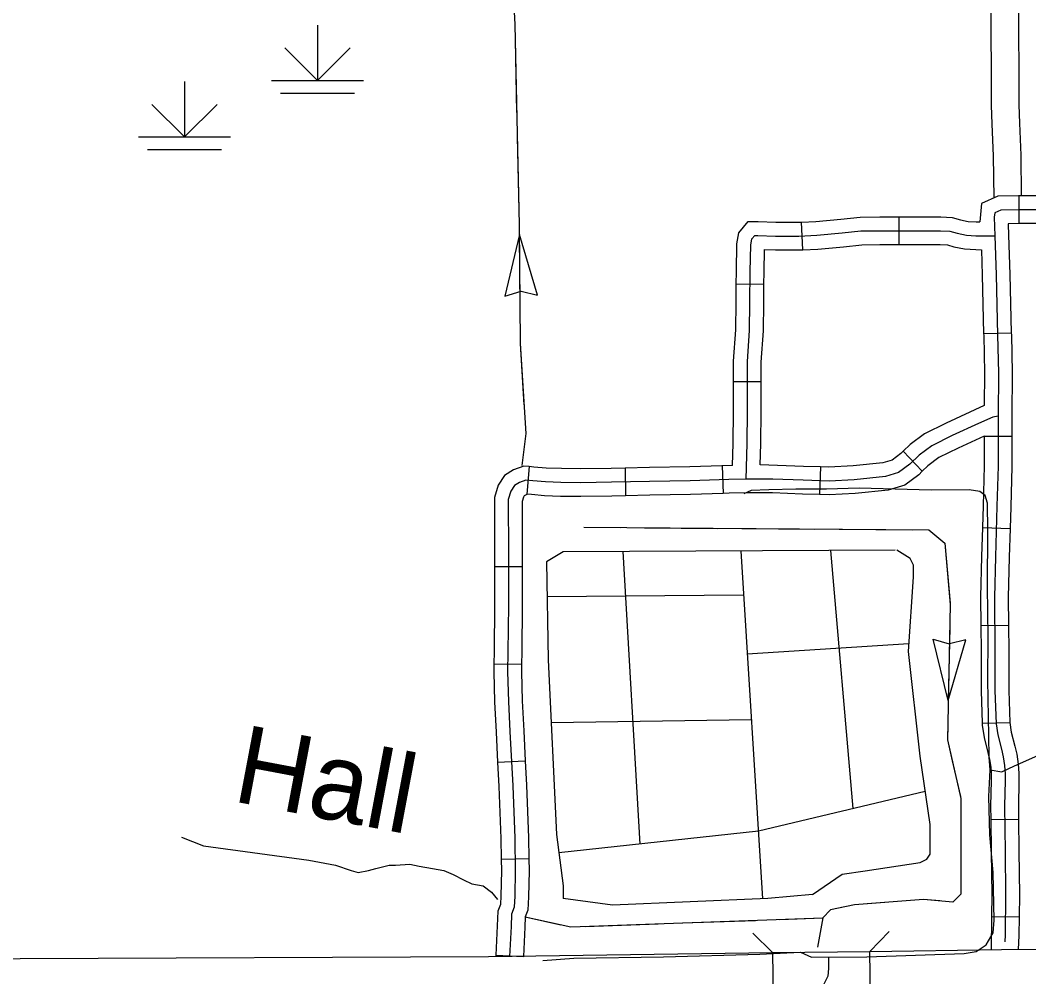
# Model space of a CAD drawing. Extents: x 1127717 to 1741049, y 2026793 to 2244711.
# Drawn here: x 1299981 to 1305449, y 2075216 to 2080400 of the extents above; entities that cross this region are included whole.
import ezdxf

# ---------------------------------------------------------------- set-up
doc = ezdxf.new("R2010")
doc.units = 0
for name, color, linetype in [('15', 7, 'Continuous'), ('32', 7, 'Continuous'), ('35', 7, 'Continuous'), ('37', 7, 'Continuous'), ('43', 7, 'Continuous'), ('44', 7, 'Continuous'), ('46', 7, 'Continuous')]:
    doc.layers.add(name, color=color, linetype=linetype)

msp = doc.modelspace()

# ---------------------------------------------------------------- linework, layer by layer
at = {"layer": '15'}
msp.add_line((1304059.9, 2075347.2), (1304063.2, 2075097.2), dxfattribs=at)
for points in [[(1304587.9, 2075354.2), (1305301.1, 2075363.7), (1308857.7, 2075384.3), (1311516.4, 2075411.9), (1312660.7, 2075431.7)], [(1291960.3, 2075242.5), (1293674.3, 2075245.9), (1294820.5, 2075264.7), (1298229, 2075302), (1299981.5, 2075316.3), (1302519.4, 2075326.7), (1304059.9, 2075347.2)], [(1304059.9, 2075347.2), (1304587.9, 2075354.2)], [(1304591.2, 2075104.2), (1304587.9, 2075354.2)]]:
    msp.add_lwpolyline(points, dxfattribs=at)
at = {"layer": '32'}
for p, q in [((1305394.8, 2079448.3), (1305394.8, 2079298.3)), ((1304747, 2079184.5), (1304747, 2079334.5)), ((1304223.7, 2079156.3), (1304216.7, 2079306.2)), ((1304013, 2078968), (1303863.1, 2078969.4)), ((1305204.2, 2078702.4), (1305354.2, 2078705.9)), ((1303998.4, 2078441.2), (1303848.4, 2078441.2)), ((1305207.4, 2078146.4), (1305357.4, 2078146.2)), ((1304767.5, 2078064), (1304871.9, 2077956.3)), ((1302740.4, 2077980.9), (1302728.5, 2077831.4)), ((1303260.3, 2077973.1), (1303263.7, 2077823.1)), ((1303787.1, 2077985.5), (1303792.6, 2077835.6)), ((1304320.1, 2077979.1), (1304315.2, 2077829.2)), ((1305197.9, 2077650.4), (1305347.8, 2077646.2)), ((1302553.5, 2077438.8), (1302703.5, 2077438.8)), ((1305188.9, 2077119.7), (1305338.9, 2077121.3)), ((1302549.5, 2076911.9), (1302699.5, 2076909.8)), ((1305196.4, 2076590.1), (1305346.3, 2076595.1)), ((1302569.7, 2076379.4), (1302719.5, 2076387.2)), ((1305243.3, 2076068.6), (1305393.3, 2076070.5)), ((1302589.1, 2075854.4), (1302739.1, 2075857)), ((1305246.9, 2075542.7), (1305396.9, 2075540.6)), ((1302559.9, 2075334.1), (1302709.8, 2075327.1))]:
    msp.add_line(p, q, dxfattribs=at)
for points in [[(1308772.4, 2080174.4), (1308789, 2080090.4), (1308816.5, 2079948.7), (1308827.1, 2079529.8), (1308831.3, 2079421.9), (1308824.9, 2079394.4), (1308803.8, 2079375.4), (1308784.8, 2079369), (1308742.5, 2079373.3), (1308638.8, 2079377.5), (1308408.3, 2079379.6), (1307993, 2079377.5), (1307525.6, 2079375.4), (1306681.8, 2079371.2), (1306251.9, 2079373.3), (1305894.5, 2079373.3), (1305393.3, 2079373.3), (1305298.1, 2079371.2), (1305264.3, 2079356.3), (1305262.2, 2079333.1), (1305264.2, 2079231.9)], [(1305394.8, 2079448.3), (1305392.5, 2079448.3), (1305281.7, 2079445.8), (1305193.6, 2079407.3), (1305184.5, 2079306.9)], [(1305922.8, 2079448.3), (1305894.5, 2079448.3), (1305394.8, 2079448.3)], [(1304216.7, 2079306.2), (1304294.8, 2079309.8), (1304430.4, 2079321.9), (1304534.1, 2079332.9), (1304640.7, 2079334.5), (1304747, 2079334.5)], [(1304747, 2079334.5), (1304812.7, 2079334.5), (1304972.6, 2079334.5), (1305033, 2079330.8), (1305078.2, 2079318.6), (1305121.2, 2079309.5), (1305163.9, 2079306.9), (1305184.5, 2079306.9)], [(1303863.1, 2078969.4), (1303863.7, 2079038.6), (1303866.9, 2079188.9), (1303877.6, 2079247.9), (1303928, 2079308.4), (1303981.2, 2079308.4), (1304077.6, 2079305.4), (1304200.2, 2079305.4), (1304216.7, 2079306.2)], [(1305394.8, 2079298.3), (1305394.1, 2079298.3), (1305337.9, 2079297), (1305339.2, 2079233.4)], [(1305922.8, 2079298.3), (1305894.5, 2079298.3), (1305394.8, 2079298.3)], [(1303916.3, 2077913.3), (1303921.8, 2078105.7), (1303923.4, 2078281.8), (1303923.4, 2078549.8), (1303935.6, 2078719), (1303937.1, 2078869), (1303938.7, 2079037.5), (1303941.7, 2079181.4), (1303947.9, 2079215.1), (1303963.2, 2079233.4), (1303980, 2079233.4), (1304076.4, 2079230.4), (1304201.9, 2079230.4), (1304299.9, 2079235), (1304437.7, 2079247.2), (1304538.7, 2079257.9), (1304641.2, 2079259.5), (1304812.7, 2079259.5), (1304970.3, 2079259.5), (1305020.8, 2079256.4), (1305060.6, 2079245.7), (1305111.1, 2079235), (1305161.6, 2079231.9), (1305264.2, 2079231.9)], [(1305264.2, 2079231.9), (1305271.8, 2079020.6), (1305279.5, 2078692.9), (1305284.1, 2078489.3), (1305282.5, 2078254.7), (1305282.2, 2077983.4), (1305276.1, 2077766), (1305268.5, 2077491.9), (1305262.3, 2077272.3), (1305265.4, 2076979.9), (1305265.4, 2076767.1), (1305271.5, 2076586.4), (1305280.7, 2076527.6), (1305300.6, 2076449.5), (1305309.8, 2076408.1), (1305317.4, 2076360.7), (1305320.5, 2076316.3), (1305320.5, 2076279.5), (1305317.4, 2076140.2), (1305320.5, 2075895.2), (1305323.6, 2075660.2), (1305320.5, 2075442.8), (1305318.9, 2075406)], [(1305339.1, 2079234.6), (1305346.8, 2079022.9), (1305354.2, 2078705.9)], [(1304013, 2078968), (1304013.7, 2079036.3), (1304016.2, 2079157.3), (1304075.2, 2079155.4), (1304203.7, 2079155.4), (1304223.7, 2079156.3)], [(1304223.7, 2079156.3), (1304305, 2079160.1), (1304444.9, 2079172.6), (1304543.2, 2079183), (1304641.8, 2079184.5), (1304747, 2079184.5)], [(1304747, 2079184.5), (1304812.7, 2079184.5), (1304968, 2079184.5), (1305008.7, 2079182), (1305043.1, 2079172.8), (1305101, 2079160.5), (1305191.9, 2079154.9)], [(1305191.9, 2079154.9), (1305196.9, 2079018.4), (1305204.2, 2078702.4)], [(1303848.4, 2078441.2), (1303848.4, 2078552.5), (1303860.6, 2078722.1), (1303862.1, 2078869.8), (1303863.1, 2078969.4)], [(1303998.4, 2078441.2), (1303998.4, 2078547.1), (1304010.6, 2078715.9), (1304012.1, 2078868.3), (1304013, 2078968)], [(1305204.2, 2078702.4), (1305204.5, 2078691.2), (1305209.1, 2078488.7), (1305207.9, 2078311.5)], [(1305354.2, 2078705.9), (1305354.5, 2078694.7), (1305359.1, 2078489.9), (1305357.5, 2078254.4), (1305357.5, 2078176.1)], [(1303843.4, 2077987.5), (1303846.8, 2078107.1), (1303848.4, 2078282.2), (1303848.4, 2078441.2)], [(1303993.6, 2077990.9), (1303996.8, 2078104.3), (1303998.4, 2078281.5), (1303998.4, 2078441.2)], [(1305207.9, 2078311.5), (1305000.7, 2078216.7), (1304883.6, 2078158.2), (1304805.5, 2078100.8), (1304767.5, 2078064)], [(1305282.5, 2078254.7), (1305253.5, 2078248.6), (1305176.9, 2078214.9), (1305033.1, 2078149.1), (1304922.9, 2078093.9), (1304854, 2078043.4), (1304803.5, 2077994.4), (1304742.2, 2077948.5), (1304671.8, 2077927), (1304502.5, 2077910.2), (1304366.3, 2077902.5), (1304225.5, 2077907.1), (1304061.7, 2077913.3), (1303916.3, 2077913.3), (1303823, 2077911.7), (1303613.3, 2077904.1), (1303393.8, 2077901), (1303187.1, 2077896.4), (1303020.3, 2077893.3), (1302913.2, 2077894.9), (1302829, 2077897.9), (1302760.1, 2077904.1), (1302721.8, 2077907.1), (1302688.2, 2077894.9), (1302660.6, 2077878), (1302640.7, 2077847.4), (1302626.9, 2077803), (1302626.9, 2077736.2), (1302628.5, 2077577), (1302628.5, 2077414.7), (1302628.5, 2077231), (1302625.4, 2076976.8), (1302623.9, 2076869), (1302628.5, 2076708.2), (1302636.1, 2076545.9), (1302651.4, 2076251.2), (1302662.1, 2075967.9), (1302665.2, 2075790.3), (1302662.1, 2075652.5), (1302659.1, 2075592.8), (1302645.3, 2075556), (1302642.2, 2075488.7), (1302634.7, 2075327.1)], [(1305357.5, 2078176.1), (1305357.2, 2077982.3), (1305351.1, 2077763.9), (1305347.8, 2077646.2)], [(1305207.4, 2078146.4), (1305065.4, 2078081.4), (1304962.1, 2078029.7), (1304902.5, 2077986), (1304871.9, 2077956.3)], [(1305207.4, 2078146.4), (1305207.2, 2077984.5), (1305201.1, 2077768.1), (1305197.9, 2077650.4)], [(1304767.5, 2078064), (1304754.7, 2078051.5), (1304707.8, 2078016.4), (1304657.1, 2078000.9), (1304496.7, 2077985), (1304365.4, 2077977.6), (1304320.1, 2077979.1)], [(1302740.4, 2077980.9), (1302711.5, 2077983.2), (1302655.5, 2077962.8), (1302607, 2077933.2), (1302572.2, 2077879.6), (1302551.9, 2077814.4), (1302551.9, 2077735.9), (1302553.5, 2077576.6), (1302553.5, 2077438.8)], [(1303260.3, 2077973.1), (1303185.6, 2077971.4), (1303020.2, 2077968.4), (1302915.1, 2077969.9), (1302833.7, 2077972.8), (1302766.4, 2077978.8), (1302740.4, 2077980.9)], [(1303843.4, 2077987.5), (1303611.4, 2077979), (1303392.4, 2077976), (1303260.3, 2077973.1)], [(1304320.1, 2077979.1), (1304228.1, 2077982.1), (1303993.6, 2077990.9)], [(1304871.9, 2077956.3), (1304852.3, 2077937.3), (1304776.7, 2077880.6), (1304686.6, 2077853.1), (1304508.4, 2077835.4), (1304367.2, 2077827.5), (1304315.2, 2077829.2)], [(1302732.1, 2077831.1), (1302720.9, 2077827), (1302714.2, 2077822.9), (1302709.3, 2077815.3), (1302701.9, 2077791.6), (1302701.9, 2077736.6), (1302703.5, 2077577.4), (1302703.5, 2077438.8)], [(1303263.7, 2077823.1), (1303188.7, 2077821.4), (1303020.5, 2077818.3), (1302911.3, 2077819.9), (1302824.3, 2077823.1), (1302753.8, 2077829.3), (1302728.5, 2077831.4)], [(1303792.6, 2077835.6), (1303615.2, 2077829.1), (1303395.1, 2077826), (1303263.7, 2077823.1)], [(1304315.2, 2077829.2), (1304222.9, 2077832.2), (1304060.3, 2077838.3), (1303916.9, 2077838.3), (1303824.9, 2077836.7), (1303792.6, 2077835.6)], [(1305197.9, 2077650.4), (1305193.5, 2077494), (1305187.3, 2077273), (1305188.9, 2077119.7)], [(1305347.8, 2077646.2), (1305343.4, 2077489.8), (1305337.4, 2077271.7), (1305338.9, 2077121.3)], [(1302553.5, 2077438.8), (1302553.5, 2077414.7), (1302553.5, 2077231.4), (1302550.4, 2076977.8), (1302549.5, 2076911.9)], [(1302703.5, 2077438.8), (1302703.5, 2077414.7), (1302703.5, 2077230.5), (1302700.4, 2076975.8), (1302699.5, 2076909.8)], [(1305188.9, 2077119.7), (1305190.4, 2076979.5), (1305190.4, 2076765.8), (1305196.4, 2076590.1)], [(1305338.9, 2077121.3), (1305340.4, 2076980.3), (1305340.4, 2076768.3), (1305346.3, 2076595.1)], [(1302549.5, 2076911.9), (1302548.9, 2076868.5), (1302553.5, 2076705.4), (1302561.2, 2076542.2), (1302569.7, 2076379.4)], [(1302699.5, 2076909.8), (1302698.9, 2076869.5), (1302703.4, 2076711.1), (1302711, 2076549.6), (1302719.5, 2076387.2)], [(1305196.4, 2076590.1), (1305196.7, 2076579.3), (1305207.2, 2076512.5), (1305227.6, 2076432.1), (1305236.1, 2076394), (1305242.9, 2076352.1), (1305245.5, 2076313.7), (1305245.5, 2076280.4), (1305242.4, 2076140.5), (1305243.3, 2076068.6)], [(1305346.3, 2076595.1), (1305346.3, 2076593.5), (1305354.3, 2076542.7), (1305373.6, 2076466.9), (1305383.5, 2076422.3), (1305392, 2076369.2), (1305395.5, 2076318.9), (1305395.5, 2076278.7), (1305392.5, 2076139.8), (1305393.3, 2076070.5)], [(1302569.7, 2076379.4), (1302576.5, 2076247.8), (1302587.2, 2075965.8), (1302589.1, 2075854.4)], [(1302719.5, 2076387.2), (1302726.4, 2076254.5), (1302737.1, 2075970), (1302739.1, 2075857)], [(1305243.3, 2076068.6), (1305245.5, 2075894.3), (1305248.6, 2075660.2), (1305246.9, 2075542.7)], [(1305393.3, 2076070.5), (1305395.5, 2075896.2), (1305398.6, 2075660.1), (1305396.9, 2075540.6)], [(1302589.1, 2075854.4), (1302590.2, 2075790.5), (1302587.2, 2075655.2), (1302584.8, 2075608.2), (1302570.9, 2075571.3), (1302567.3, 2075492.1), (1302559.9, 2075334.1)], [(1302739.1, 2075857), (1302740.2, 2075790.1), (1302737.1, 2075649.7), (1302733.4, 2075577.3), (1302719.7, 2075540.8), (1302717.2, 2075485.2), (1302709.8, 2075327.1)], [(1305246.9, 2075542.7), (1305244.4, 2075362.9)], [(1305396.9, 2075540.6), (1305395.5, 2075440.5), (1305392.1, 2075364.2)], [(1302559.9, 2075334.1), (1302559.8, 2075330.6)], [(1302709.8, 2075327.1), (1302709.6, 2075323.6)]]:
    msp.add_lwpolyline(points, dxfattribs=at)
at = {"layer": '35'}
for points in [[(1304724.8, 2077528), (1302924.4, 2077519), (1302834.4, 2077464.9), (1302843.4, 2076933.6), (1302888.4, 2075988.1), (1302924.4, 2075708.9), (1302924.4, 2075640.5)], [(1303248.4, 2077520.6), (1303340.3, 2075935.8)], [(1303887.5, 2077523.8), (1304006.1, 2075639.3)], [(1304276.3, 2075662.6), (1304436.7, 2075772), (1304562.7, 2075790), (1304859.8, 2075835), (1304895.8, 2075853), (1304913.8, 2075880), (1304913.8, 2076042.1), (1304859.8, 2076411.3), (1304796.8, 2076978.7), (1304823.8, 2077383.9), (1304823.8, 2077446.9), (1304805.8, 2077482.9), (1304733.8, 2077528)], [(1304373.7, 2077526.2), (1304496.1, 2076127.7)], [(1303902.5, 2077285.2), (1302837.6, 2077275.7)], [(1303922.5, 2076967.3), (1304799.7, 2077021.7)], [(1303945.1, 2076609.1), (1302859.7, 2076591.8)], [(1304887.6, 2076221), (1303983.1, 2076005.3), (1302901.3, 2075888.4)], [(1300856.3, 2075972.7), (1300974.9, 2075925.2), (1301545.8, 2075848.5), (1301691.2, 2075820.5), (1301775.1, 2075792.6), (1301814.2, 2075781.4), (1301870.2, 2075792.6), (1301909.3, 2075803.7), (1301982, 2075820.5), (1302015.6, 2075820.5), (1302093.9, 2075826.1), (1302144.2, 2075814.9), (1302217, 2075803.7), (1302278.5, 2075792.6), (1302328.8, 2075770.2), (1302384.7, 2075742.2), (1302429.5, 2075719.8), (1302491, 2075708.6), (1302535.8, 2075675.1), (1302569.3, 2075635.9)], [(1304276.3, 2075662.6), (1304034.3, 2075640.5), (1303192.3, 2075604.9), (1302924.4, 2075640.5)]]:
    msp.add_lwpolyline(points, dxfattribs=at)
at = {"layer": '37'}
for points in [[(1303952.4, 2075451.8), (1304059.9, 2075347.2)], [(1304587.9, 2075354.2), (1304692.5, 2075461.7)]]:
    msp.add_lwpolyline(points, dxfattribs=at)
at = {"layer": '43'}
for p, q in [((1302688.2, 2079239.4), (1302609, 2078905.5)), ((1302786.6, 2078910.6), (1302688.2, 2079239.4)), ((1302609, 2078905.5), (1302696.5, 2078931.6)), ((1302697.7, 2078931.7), (1302786.6, 2078910.6)), ((1305012.5, 2076713), (1304930.2, 2077046.2)), ((1304930.2, 2077046.2), (1305018, 2077020.8)), ((1305012.5, 2076713), (1305107.8, 2077042.7)), ((1305107.8, 2077042.7), (1305019.2, 2077020.8))]:
    msp.add_line(p, q, dxfattribs=at)
for points in [[(1302702.5, 2077987.6), (1302723.6, 2078161.1), (1302694, 2078647.6), (1302687.7, 2079290.8), (1302677.1, 2079784.1), (1302664.4, 2080376.5), (1302658.1, 2080514)], [(1302674.6, 2079899.2), (1302666.2, 2080295.2)], [(1302686, 2079371.4), (1302677.5, 2079767.3)], [(1302692.1, 2078843.4), (1302688.2, 2079239.4)], [(1302714.2, 2078316), (1302694, 2078647.6), (1302693.4, 2078711.4)], [(1302815, 2075305), (1302982.2, 2075317.3), (1303469.1, 2075324.7), (1303990.4, 2075339.4), (1304211.7, 2075349.3), (1304270.7, 2075322.2), (1304570.7, 2075324.7), (1305099.3, 2075341.9), (1305163.2, 2075354.2), (1305217.3, 2075388.6), (1305256.7, 2075455.1), (1305261.6, 2075523.9), (1305256.7, 2075782.2), (1305237, 2075986.4), (1305232.1, 2076193), (1305239.5, 2076338.2), (1305234.6, 2076407.1), (1305232.1, 2076522.7), (1305227.2, 2076825.3), (1305229.6, 2077056.5), (1305224.7, 2077332), (1305227.2, 2077632.1), (1305224.7, 2077782.2), (1305212.4, 2077824), (1305182.9, 2077846.2), (1305126.4, 2077856), (1304919.8, 2077853.5), (1304528.9, 2077863.4), (1304351.8, 2077858.4), (1304187.1, 2077858.4), (1304039.5, 2077856), (1303943.6, 2077851.1), (1303904.3, 2077833.8)], [(1305239.5, 2076338.2), (1305302.4, 2076326.9), (1305371.8, 2076359.8), (1305514.2, 2076421.9), (1305748, 2076505.9), (1306018.2, 2076597.3), (1306387.1, 2076725.2), (1306851, 2076885.9), (1307340.4, 2077054), (1307581.4, 2077160), (1307906.5, 2077342.7), (1308202.3, 2077510.8), (1308381.3, 2077613.1), (1308542, 2077686.1), (1308669.8, 2077733.6), (1308739.2, 2077751.9), (1308786.7, 2077733.6), (1308834.2, 2077678.8), (1308863.4, 2077587.5), (1308870.7, 2077466.9), (1308870.7, 2077309.8), (1308875.2, 2077213.9)], [(1303036.1, 2077652), (1304907.6, 2077637.6), (1304993.9, 2077565.6), (1305022.7, 2077234.4), (1305008.3, 2076499.9), (1305080.3, 2076183.1), (1305080.3, 2075664.7), (1305037.1, 2075621.5), (1304878.8, 2075635.9), (1304504.5, 2075607.1), (1304374.9, 2075578.3), (1304331.7, 2075535.1), (1304302.9, 2075376.6)], [(1303036.1, 2077652), (1303234, 2077650.5)], [(1303366, 2077649.5), (1303762, 2077646.5)], [(1303894, 2077645.4), (1304290, 2077642.4)], [(1304422, 2077641.4), (1304818, 2077638.3)], [(1304940.2, 2077610.5), (1304993.9, 2077565.6), (1305022.2, 2077240.9)], [(1305020.3, 2077108.9), (1305012.5, 2076713)], [(1305009.9, 2076581), (1305008.3, 2076499.9), (1305034.2, 2076386)], [(1305034.2, 2076386), (1305078.1, 2076192.9)], [(1305080.3, 2076061.1), (1305080.3, 2075665.1)], [(1304967, 2075627.9), (1304878.8, 2075635.9), (1304572.2, 2075612.3)], [(1304442, 2075593.2), (1304374.9, 2075578.3), (1304331.7, 2075535.1), (1304302.9, 2075376.6)], [(1302719.7, 2075540.8), (1302967, 2075486.3), (1304331.7, 2075535.1)], [(1302719.7, 2075540.8), (1302913.1, 2075498.2)], [(1303043.7, 2075489), (1303439.5, 2075503.2)], [(1303571.4, 2075507.9), (1303967.1, 2075522)], [(1304099, 2075526.7), (1304331.7, 2075535.1)], [(1304364, 2075323), (1304364, 2075261.8), (1304359.3, 2075219.4), (1304335.7, 2075172.3)]]:
    msp.add_lwpolyline(points, dxfattribs=at)
at = {"layer": '44'}
for p, q in [((1301593.2, 2080373.3), (1301593.2, 2080073.3)), ((1301593.2, 2080073.3), (1301416.4, 2080250.1)), ((1301593.2, 2080073.3), (1301770, 2080250.1)), ((1300872, 2080067.2), (1300872, 2079767.2)), ((1301343.2, 2080073.3), (1301843.2, 2080073.3)), ((1301393.2, 2080005.2), (1301793.2, 2080005.2)), ((1300872, 2079767.2), (1300695.2, 2079944)), ((1300872, 2079767.2), (1301048.8, 2079944)), ((1300622, 2079767.2), (1301122, 2079767.2)), ((1300672, 2079699), (1301072, 2079699))]:
    msp.add_line(p, q, dxfattribs=at)
at = {"layer": '46'}
for points in [[(1305138.5, 2083053.5), (1305222, 2082855), (1305224.1, 2082812.7), (1305222, 2082512.3), (1305224.1, 2082240.6), (1305228.4, 2081690.6), (1305232.6, 2081345.8), (1305238.9, 2080865.3), (1305243.2, 2080520.5), (1305245.3, 2079938.8), (1305249.5, 2079836.6), (1305255.9, 2079665.2), (1305258.8, 2079435.8)], [(1305300, 2083056.4), (1305370.5, 2082888.9), (1305374.2, 2082815.9), (1305372, 2082512.4), (1305374.1, 2082241.8), (1305378.4, 2081692.1), (1305382.6, 2081347.7), (1305388.9, 2080867.3), (1305393.2, 2080521.7), (1305395.3, 2079942.1), (1305399.4, 2079842.4), (1305405.8, 2079669), (1305408.6, 2079448.3)]]:
    msp.add_lwpolyline(points, dxfattribs=at)

# ---------------------------------------------------------------- texts
at = {"layer": '35'}
msp.add_text('Hall', height=422.4, rotation=349.309, dxfattribs=at).set_placement((1301124.3, 2076169.2))

doc.saveas('drawing.dxf')
